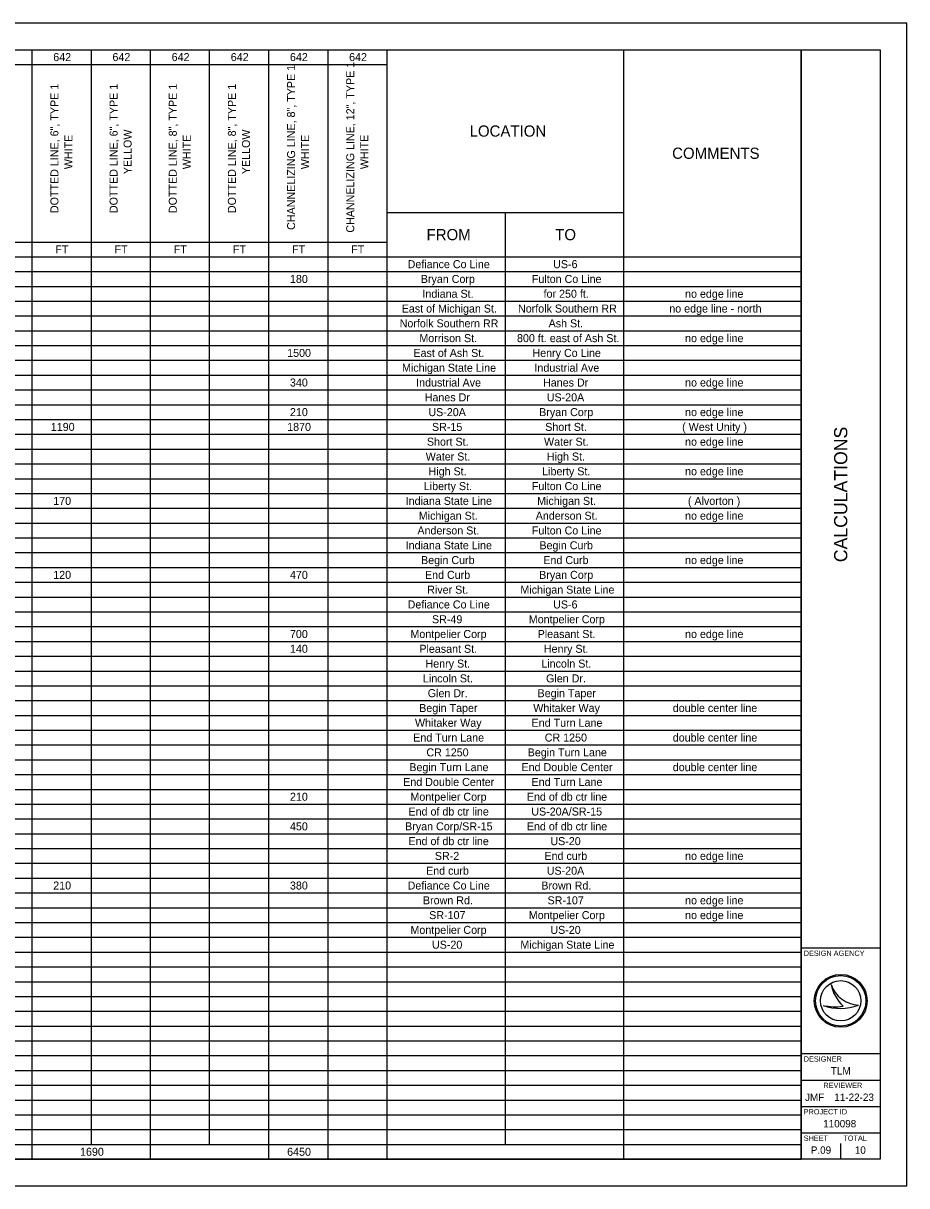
# Model space of a CAD drawing. Extents: x 0 to 34, y 0 to 22.
# Drawn here: x 17.28 to 34, y 0 to 22 of the extents above; entities that cross this region are included whole.
import ezdxf

# ---------------------------------------------------------------- set-up
doc = ezdxf.new("R2010")
doc.units = 0
for name, color, linetype in [('Default', 7, 'Continuous'), ('SH_Border', 7, 'Continuous'), ('SH_Cut_Line', 7, 'Continuous'), ('SH_Data', 7, 'Continuous')]:
    doc.layers.add(name, color=color, linetype=linetype)

msp = doc.modelspace()

# ---------------------------------------------------------------- linework, layer by layer
at = {"layer": 'Default'}
for p, q in [((1.5, 21.5), (32, 21.5)), ((17.442, 21.5), (17.442, 0.502)), ((18.562, 21.5), (18.562, 0.782)), ((19.681, 21.5), (19.681, 0.502)), ((20.801, 21.5), (20.801, 0.782)), ((21.921, 21.5), (21.921, 0.502)), ((23.041, 21.5), (23.041, 0.502)), ((24.161, 21.5), (24.161, 0.502)), ((28.64, 21.5), (28.64, 0.502)), ((32, 21.5), (32, 0.502)), ((8.483, 21.22), (24.161, 21.22)), ((24.161, 18.42), (28.64, 18.42)), ((26.401, 18.42), (26.401, 0.782)), ((8.483, 17.86), (24.161, 17.86)), ((1.5, 17.58), (32, 17.58)), ((2.505, 17.3), (32, 17.3)), ((2.505, 17.021), (32, 17.021)), ((2.505, 16.741), (32, 16.741)), ((2.505, 16.461), (32, 16.461)), ((2.505, 16.181), (32, 16.181)), ((2.505, 15.901), (32, 15.901)), ((2.505, 15.621), (32, 15.621)), ((2.505, 15.341), (32, 15.341)), ((2.505, 15.061), (32, 15.061)), ((2.505, 14.781), (32, 14.781)), ((2.505, 14.501), (32, 14.501)), ((2.505, 14.221), (32, 14.221)), ((2.505, 13.941), (32, 13.941)), ((2.505, 13.661), (32, 13.661)), ((2.505, 13.381), (32, 13.381)), ((2.505, 13.101), (32, 13.101)), ((2.505, 12.821), (32, 12.821)), ((2.505, 12.541), (32, 12.541)), ((2.505, 12.261), (32, 12.261)), ((2.505, 11.981), (32, 11.981)), ((2.505, 11.701), (32, 11.701)), ((2.505, 11.421), (32, 11.421)), ((2.505, 11.141), (32, 11.141)), ((2.505, 10.861), (32, 10.861)), ((2.505, 10.581), (32, 10.581)), ((2.505, 10.301), (32, 10.301)), ((2.505, 10.021), (32, 10.021)), ((2.505, 9.741), (32, 9.741)), ((2.505, 9.461), (32, 9.461)), ((2.505, 9.181), (32, 9.181)), ((2.505, 8.901), (32, 8.901)), ((2.505, 8.621), (32, 8.621)), ((2.505, 8.342), (32, 8.342)), ((2.505, 8.062), (32, 8.062)), ((2.505, 7.782), (32, 7.782)), ((2.505, 7.502), (32, 7.502)), ((2.505, 7.222), (32, 7.222)), ((2.505, 6.942), (32, 6.942)), ((2.505, 6.662), (32, 6.662)), ((2.505, 6.382), (32, 6.382)), ((2.505, 6.102), (32, 6.102)), ((2.505, 5.822), (32, 5.822)), ((2.505, 5.542), (32, 5.542)), ((2.505, 5.262), (32, 5.262)), ((2.505, 4.982), (32, 4.982)), ((2.505, 4.702), (32, 4.702)), ((1.5, 4.422), (32, 4.422)), ((1.5, 4.142), (32, 4.142)), ((1.5, 3.862), (32, 3.862)), ((1.5, 3.582), (32, 3.582)), ((1.5, 3.302), (32, 3.302)), ((1.5, 3.022), (32, 3.022)), ((1.5, 2.742), (32, 2.742)), ((1.5, 2.462), (32, 2.462)), ((1.5, 2.182), (32, 2.182)), ((1.5, 1.902), (32, 1.902)), ((1.5, 1.622), (32, 1.622)), ((1.5, 1.342), (32, 1.342)), ((1.5, 1.062), (32, 1.062)), ((1.5, 0.782), (32, 0.782)), ((1.5, 0.502), (32, 0.502))]:
    msp.add_line(p, q, dxfattribs=at)
at = {"layer": 'SH_Border'}
for p, q in [((32, 0.5), (32, 21.5)), ((32, 4.5), (33.5, 4.5)), ((32, 2.5), (33.5, 2.5)), ((32, 2), (33.5, 2)), ((32, 1.5), (33.5, 1.5)), ((32, 1), (33.5, 1))]:
    msp.add_line(p, q, dxfattribs=at)
msp.add_lwpolyline([(1.5, 21.5), (33.5, 21.5), (33.5, 0.5), (1.5, 0.5)], close=True, dxfattribs=at)
at = {"layer": 'SH_Cut_Line'}
msp.add_lwpolyline([(0, 0), (34, 0), (34, 22), (0, 22)], close=True, dxfattribs=at)
at = {"layer": 'SH_Data'}
for p, q in [((32.567, 3.81), (32.567, 3.81)), ((32.417, 3.41), (32.417, 3.41)), ((32.75, 3.5), (32.75, 3.5)), ((33.087, 3.419), (33.087, 3.419)), ((32.375, 0.675), (32.375, 0.675)), ((32.75, 0.5), (32.75, 0.8))]:
    msp.add_line(p, q, dxfattribs=at)
for radius in [0.5, 0.477, 0.477, 0.382]:
    msp.add_circle((32.75, 3.5), radius, dxfattribs=at)
for centre, radius, start, end in [((33.116, 3.998), 0.58, 198.9257, 198.9319), ((33.347, 3.97), 0.796, 191.6379, 191.6421), ((33.116, 3.998), 0.58, 198.9319, 267.1657), ((33.347, 3.97), 0.796, 191.6421, 226.0947), ((32.739, 4.37), 1.013, 251.4576, 290.0832), ((32.648, 4.654), 1.266, 259.4964, 259.4995), ((32.739, 4.37), 1.013, 251.4527, 251.4576), ((32.648, 4.654), 1.266, 259.4995, 276.6672)]:
    msp.add_arc(centre, radius, start, end, dxfattribs=at)

# ---------------------------------------------------------------- texts
at = {"layer": 'Default'}
for s, height, p in [('642', 0.1515, (17.848, 21.284)), ('642', 0.1515, (18.968, 21.284)), ('642', 0.1515, (20.088, 21.284)), ('642', 0.1515, (21.207, 21.284)), ('642', 0.1515, (22.327, 21.284)), ('642', 0.1515, (23.447, 21.284)), ('LOCATION', 0.2121, (25.727, 19.854)), ('COMMENTS', 0.2121, (29.56, 19.434)), ('FROM', 0.2121, (24.913, 17.894)), ('TO', 0.2121, (27.347, 17.894)), ('FT', 0.1515, (17.887, 17.645)), ('FT', 0.1515, (19.007, 17.645)), ('FT', 0.1515, (20.127, 17.645)), ('FT', 0.1515, (21.247, 17.645)), ('FT', 0.1515, (22.367, 17.645)), ('FT', 0.1515, (23.486, 17.645)), ('Defiance Co Line', 0.15151, (24.554, 17.365)), ('US-6', 0.1515, (27.308, 17.365)), ('180', 0.1515, (22.327, 17.085)), ('Bryan Corp', 0.1515, (24.803, 17.085)), ('Fulton Co Line', 0.15151, (26.905, 17.085)), ('Indiana St.', 0.15151, (24.834, 16.805)), ('for 250 ft.', 0.15151, (27.127, 16.805)), ('no edge line', 0.15151, (29.805, 16.805)), ('East of Michigan St.', 0.15151, (24.442, 16.525)), ('Norfolk Southern RR', 0.15151, (26.643, 16.525)), ('no edge line - north', 0.15151, (29.506, 16.525)), ('Norfolk Southern RR', 0.15151, (24.403, 16.245)), ('Ash St.', 0.1515, (27.222, 16.245)), ('Morrison St.', 0.15151, (24.776, 15.965)), ('800 ft. east of Ash St.', 0.15151, (26.624, 15.965)), ('no edge line', 0.15151, (29.805, 15.965)), ('East of Ash St.', 0.15151, (24.664, 15.685)), ('Henry Co Line', 0.15151, (26.916, 15.685)), ('1500', 0.1515, (22.274, 15.685)), ('Michigan State Line', 0.15151, (24.448, 15.405)), ('Industrial Ave', 0.15151, (26.954, 15.405)), ('340', 0.1515, (22.327, 15.125)), ('Industrial Ave', 0.15151, (24.715, 15.125)), ('Hanes Dr', 0.1515, (27.117, 15.125)), ('no edge line', 0.15151, (29.805, 15.125)), ('Hanes Dr', 0.1515, (24.877, 14.845)), ('US-20A', 0.1515, (27.187, 14.845)), ('210', 0.1515, (22.327, 14.565)), ('US-20A', 0.1515, (24.947, 14.565)), ('Bryan Corp', 0.1515, (27.043, 14.565)), ('no edge line', 0.15151, (29.805, 14.565)), ('1190', 0.1515, (17.801, 14.285)), ('1870', 0.1515, (22.274, 14.285)), ('SR-15', 0.1515, (25.015, 14.285)), ('Short St.', 0.1515, (27.158, 14.285)), ('( West Unity )', 0.15151, (29.749, 14.285)), ('Short St.', 0.1515, (24.919, 14.005)), ('Water St.', 0.1515, (27.135, 14.005)), ('no edge line', 0.15151, (29.805, 14.005)), ('Water St.', 0.1515, (24.896, 13.725)), ('High St.', 0.1515, (27.19, 13.725)), ('High St.', 0.1515, (24.95, 13.445)), ('Liberty St.', 0.15151, (27.1, 13.445)), ('no edge line', 0.15151, (29.805, 13.445)), ('Liberty St.', 0.15151, (24.86, 13.165)), ('Fulton Co Line', 0.15151, (26.905, 13.165)), ('170', 0.1515, (17.847, 12.885)), ('Indiana State Line', 0.15151, (24.517, 12.885)), ('Michigan St.', 0.15151, (27.005, 12.885)), ('( Alvorton )', 0.15151, (29.858, 12.885)), ('Michigan St.', 0.15151, (24.765, 12.605)), ('Anderson St.', 0.15151, (26.978, 12.605)), ('no edge line', 0.15151, (29.805, 12.605)), ('Anderson St.', 0.15151, (24.739, 12.325)), ('Fulton Co Line', 0.15151, (26.905, 12.325)), ('Indiana State Line', 0.15151, (24.517, 12.045)), ('Begin Curb', 0.1515, (27.048, 12.045)), ('Begin Curb', 0.1515, (24.808, 11.765)), ('End Curb', 0.1515, (27.122, 11.765)), ('no edge line', 0.15151, (29.805, 11.765)), ('120', 0.1515, (17.847, 11.485)), ('470', 0.1515, (22.327, 11.485)), ('End Curb', 0.1515, (24.882, 11.485)), ('Bryan Corp', 0.1515, (27.043, 11.485)), ('River St.', 0.1515, (24.924, 11.205)), ('Michigan State Line', 0.15151, (26.688, 11.205)), ('Defiance Co Line', 0.15151, (24.554, 10.925)), ('US-6', 0.1515, (27.308, 10.925)), ('SR-49', 0.1515, (25.015, 10.645)), ('Montpelier Corp', 0.15151, (26.847, 10.645)), ('700', 0.1515, (22.327, 10.366)), ('Montpelier Corp', 0.15151, (24.607, 10.366)), ('Pleasant St.', 0.15151, (27.015, 10.366)), ('no edge line', 0.15151, (29.805, 10.366)), ('140', 0.1515, (22.327, 10.086)), ('Pleasant St.', 0.15151, (24.776, 10.086)), ('Henry St.', 0.1515, (27.132, 10.086)), ('Henry St.', 0.1515, (24.892, 9.806)), ('Lincoln St.', 0.15151, (27.084, 9.806)), ('Lincoln St.', 0.15151, (24.844, 9.526)), ('Glen Dr.', 0.1515, (27.174, 9.526)), ('Glen Dr.', 0.1515, (24.935, 9.246)), ('Begin Taper', 0.15151, (27.013, 9.246)), ('Begin Taper', 0.15151, (24.773, 8.966)), ('Whitaker Way', 0.15151, (26.932, 8.966)), ('double center line', 0.15151, (29.572, 8.966)), ('Whitaker Way', 0.15151, (24.693, 8.686)), ('End Turn Lane', 0.15151, (26.9, 8.686)), ('End Turn Lane', 0.15151, (24.66, 8.406)), ('CR 1250', 0.1515, (27.149, 8.406)), ('double center line', 0.15151, (29.572, 8.406)), ('CR 1250', 0.1515, (24.909, 8.126)), ('Begin Turn Lane', 0.15151, (26.826, 8.126)), ('Begin Turn Lane', 0.15151, (24.586, 7.846)), ('End Double Center', 0.15151, (26.709, 7.846)), ('double center line', 0.15151, (29.572, 7.846)), ('End Double Center', 0.15151, (24.47, 7.566)), ('End Turn Lane', 0.15151, (26.9, 7.566)), ('210', 0.1515, (22.327, 7.286)), ('Montpelier Corp', 0.15151, (24.607, 7.286)), ('End of db ctr line', 0.15151, (26.81, 7.286)), ('End of db ctr line', 0.15151, (24.57, 7.006)), ('US-20A/SR-15', 0.15151, (26.894, 7.006)), ('450', 0.1515, (22.327, 6.726)), ('Bryan Corp/SR-15', 0.15151, (24.506, 6.726)), ('End of db ctr line', 0.15151, (26.81, 6.726)), ('End of db ctr line', 0.15151, (24.57, 6.446)), ('US-20', 0.1515, (27.255, 6.446)), ('SR-2', 0.1515, (25.069, 6.166)), ('End curb', 0.1515, (27.143, 6.166)), ('no edge line', 0.15151, (29.805, 6.166)), ('End curb', 0.1515, (24.903, 5.886)), ('US-20A', 0.1515, (27.187, 5.886)), ('210', 0.1515, (17.847, 5.606)), ('380', 0.1515, (22.327, 5.606)), ('Defiance Co Line', 0.15151, (24.554, 5.606)), ('Brown Rd.', 0.1515, (27.084, 5.606)), ('Brown Rd.', 0.1515, (24.844, 5.326)), ('SR-107', 0.1515, (27.202, 5.326)), ('no edge line', 0.15151, (29.805, 5.326)), ('SR-107', 0.1515, (24.962, 5.046)), ('Montpelier Corp', 0.15151, (26.847, 5.046)), ('no edge line', 0.15151, (29.805, 5.046)), ('Montpelier Corp', 0.15151, (24.607, 4.766)), ('US-20', 0.1515, (27.255, 4.766)), ('US-20', 0.1515, (25.015, 4.486)), ('Michigan State Line', 0.15151, (26.688, 4.486)), ('1690', 0.1515, (18.354, 0.567)), ('6450', 0.1515, (22.274, 0.567))]:
    msp.add_text(s, height=height, dxfattribs=at).set_placement(p)
for s, height, p in [('CHANNELIZING LINE, 8", TYPE 1', 0.15151, (22.424, 18.089)), ('CHANNELIZING LINE, 12", TYPE 1', 0.15151, (23.544, 18.036)), ('DOTTED LINE, 6", TYPE 1', 0.15151, (17.945, 18.407)), ('DOTTED LINE, 6", TYPE 1', 0.15151, (19.065, 18.407)), ('DOTTED LINE, 8", TYPE 1', 0.15151, (20.185, 18.407)), ('DOTTED LINE, 8", TYPE 1', 0.15151, (21.304, 18.407)), ('WHITE', 0.1515, (18.21, 19.238)), ('YELLOW', 0.1515, (19.33, 19.144)), ('WHITE', 0.1515, (20.45, 19.238)), ('YELLOW', 0.1515, (21.57, 19.144)), ('WHITE', 0.1515, (22.689, 19.238)), ('WHITE', 0.1515, (23.809, 19.238))]:
    msp.add_text(s, height=height, rotation=90, dxfattribs=at).set_placement(p)
at = {"layer": 'SH_Data'}
msp.add_text('CALCULATIONS', height=0.25, rotation=90, dxfattribs=at).set_placement((32.875, 11.801))
for s, height, p in [('DESIGN AGENCY', 0.1, (32.05, 4.35)), ('DESIGNER', 0.1, (32.05, 2.35)), ('TLM', 0.14, (32.565, 2.105)), ('REVIEWER', 0.1, (32.422, 1.85)), ('JMF', 0.14, (32.075, 1.605)), ('11-22-23', 0.14, (32.629, 1.605)), ('PROJECT ID', 0.1, (32.05, 1.35)), ('110098', 0.14, (32.419, 1.105)), ('SHEET', 0.1, (32.05, 0.85)), ('TOTAL', 0.1, (32.8, 0.85)), ('P.09', 0.14, (32.184, 0.605)), ('10', 0.14, (33.017, 0.605))]:
    msp.add_text(s, height=height, dxfattribs=at).set_placement(p)

doc.saveas('drawing.dxf')
